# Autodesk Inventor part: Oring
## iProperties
Shininess: 64.0
Length Units: 11269
Angle Units: 11279
Time Units: 11290
Mass Units: 11283
Length Display Precision: 3
Angle Display Precision: 2
Compacted: True
Part Number: Oring
Document SubType Name: Modeling
Created: 2003-02
Material: Standard
Designer: hofer_a
Density: 0.0
Volumn: 0.0
Area: 0.0
PropertySet Name: Model Information
Control State: 0
Master: False
Checked Out: False
Author: hofer_a
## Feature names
1. Sweeping1
